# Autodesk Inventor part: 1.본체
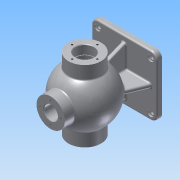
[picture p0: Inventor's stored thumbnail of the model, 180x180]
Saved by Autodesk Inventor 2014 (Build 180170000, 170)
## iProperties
Created: 2017-01
Part Number: 1.본체
Material: Aluminum 6061
Document SubType Name: Modeling
Designer: ksu
Density: 2.71 g/cm^3
Appearance: Aluminum - Flat
Mass: 1509 g
Surface Area: 1155.11 cm^2
Volume: 556.828 cm^3
Author: ksu
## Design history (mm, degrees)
sketch "Sketch1"
  geometry: L1 (-62.5, 57.5)-(62.5, 57.5); L2 (62.5, 57.5)-(62.5, -57.5); L3 (62.5, -57.5)-(-62.5, -57.5); L4 (-62.5, -57.5)-(-62.5, 57.5); L5 (-62.5, 57.5)-(62.5, -57.5); L6 (62.5, 57.5)-(-62.5, -57.5); 1 further point
  constraints: 12 end point, 2 midpoint, 2 parallel, 1 horizontal, 1 perpendicular
  dimensions: "d0" = 125 distance of L2.end L3.end; "d1" = 115 distance of L1.end L2.end
extrude "Extrusion1" new body sketch "Sketch1" distance "d2" = 10; taper "d3" = 0 deg
fillet "Fillet1" dims "d4" = 12
fillet "Fillet2" dims "d5" = 3
sketch "Sketch2"
  geometry: A1 r 9 centre (-50.5, 45.5) between (-50.5, 54.5) and (-59.5, 45.5) reference; A2 r 9 centre (-50.5, -45.5) between (-59.5, -45.5) and (-50.5, -54.5) reference; A3 r 9 centre (50.5, -45.5) between (50.5, -54.5) and (59.5, -45.5) reference; A4 r 9 centre (50.5, 45.5) between (59.5, 45.5) and (50.5, 54.5) reference; 5 further points
  constraints: 4 coincident
hole "Hole1" sketch "Sketch2" at (-50.5, 45.5), (-50.5, -45.5), (50.5, -45.5), (50.5, 45.5) diameter "d6" = 8; stored, may be unused: countersink angle "d10" = 90 deg, drill point angle "d12" = 118 deg; dims "d7" = 6, "d8" = 12, "d9" = 3, "d11" = 8
sketch "Sketch3"
  geometry: L1 (-50.5, 0)-(50.5, 0) reference; L2 (0, 150.015)-(0, -20.474); L3 (0, 138)-(0, 32); A1 r 53 centre (0, 85) between (0, 138) and (0, 32); 1 further point
  constraints: 4 end point, 2 point on circle, 2 point on line, 1 centre point, 1 collinear, 1 perpendicular
  dimensions: "d13" = 106 diameter of A1; "d14" = 85 distance from line of L1 A1.centre
revolve "Revolution1" sketch "Sketch3" stored, may be unused: angle "d15" = 90 deg
sketch "Sketch4"
  geometry: L1 (-62.5, 7)-(-62.5, 0) reference; L2 (62.5, 0)-(62.5, 7) reference; L3 (-50.5, 0)-(50.5, 0) reference; C1 r 31 at (0, 85); 1 further point
  constraints: 1 centre point
  dimensions: "d16" = 125 distance between parallel lines of L1 L2 (derived); "d17" = 62 diameter of C1; "d18" = 85 distance from line of L3 C1.centre
extrude "Extrusion2" join sketch "Sketch4" stored distance "d19" = 136; taper "d20" = 0 deg
workplane "Work Plane1"
sketch "Sketch5"
  geometry: C1 r 27 at (0, 0); 1 further point
  constraints: 1 centre point, 1 coincident
  dimensions: "d22" = 54 diameter of C1
extrude "Extrusion3" join sketch "Sketch5" distance "d23" = 65; taper "d24" = 0 deg
sketch "Sketch6"
  geometry: L1 (-59.5, 10)-(-50.5, 10) reference; L2 (50.5, 10)-(-50.5, 10) reference; L3 (50.5, 10)-(59.5, 10) reference; L4 (-50.5, 10)-(50.5, 10) reference; L5 (-52.5, 10)-(-35.28, 52.62); L6 (-62.5, 0)-(-62.5, 7) reference; L7 (52.5, 10)-(35.28, 52.62); L8 (62.5, 7)-(62.5, 0) reference; L9 (-35.28, 52.62)-(35.28, 52.62); L10 (-52.5, 10)-(52.5, 10); 1 further point
  constraints: 8 end point, 2 point on line, 1 collinear, 1 perpendicular
  dimensions: "d25" = 10 distance from line of L6 L5.start; "d26" = 22 deg angle of L6 L5; "d27" = 10 distance from line of L7.start L8; "d28" = 22 deg angle of L7 L8
extrude "Extrusion4" join sketch "Sketch6" stored distance "d29" = 8; taper "d30" = 0 deg
sketch "Sketch7"
  geometry: L1 (-45.5, 10)-(45.5, 10) reference; L2 (-51.5, 10)-(-39.5, 10) reference; L3 (-54.5, 10)-(-45.5, 10) reference; L4 (45.5, 10)-(54.5, 10) reference; L5 (-47.5, 10)-(-31.246, 50.23); L6 (-57.5, 0)-(-57.5, 7) reference; L7 (47.5, 10)-(31.246, 50.23); L8 (57.5, 7)-(57.5, 0) reference; L9 (-31.246, 50.23)-(31.246, 50.23); L10 (-47.5, 10)-(47.5, 10); A1 r 3 centre (-54.5, 7) between (-54.5, 10) and (-57.5, 7) reference; A2 r 3 centre (54.5, 7) between (57.5, 7) and (54.5, 10) reference; 1 further point
  constraints: 8 end point, 2 point on line, 1 collinear, 1 perpendicular
  dimensions: "d31" = 10 distance from line of L6 L5.start; "d32" = 22 deg angle of L6 L5; "d33" = 22 deg angle of L7 L8; "d34" = 10 distance from line of L8 L7.start
extrude "Extrusion5" join sketch "Sketch7" stored distance "d35" = 8; taper "d36" = 0 deg
fillet "Fillet3" dims "d37" = 3
fillet "Fillet4" dims "d38" = 3
fillet "Fillet5" dims "d39" = 3
sketch "Sketch8"
  geometry: L1 (-103.502, 85)-(116.5, 85); L2 (-43, 85)-(43, 85); A1 r 43 centre (0, 85) between (43, 85) and (-43, 85); 1 further point
  constraints: 4 end point, 3 point on line, 2 point on circle, 1 centre point, 1 collinear, 1 horizontal
  dimensions: "d40" = 85 distance from line of point (0, 0) L1; "d41" = 86 diameter of A1
revolve "Revolution2" sketch "Sketch8" stored, may be unused: angle "d42" = 90 deg
sketch "Sketch9"
  geometry: C1 r 31 at (0, 0) reference; C2 r 17.5 at (0, 0); 1 further point
  constraints: 1 centre point, 1 coincident
  dimensions: "d43" = 35 diameter of C2
extrude "Extrusion6" cut sketch "Sketch9" stored distance "d44" = 8; taper "d45" = 0 deg
sketch "Sketch10"
  geometry: L1 (68, 102.5)-(68, 67.5) reference; L2 (-76.217, 85)-(110.893, 85); L3 (52, 85)-(50.25, 85); L4 (50.25, 85)-(50.25, 66.5); L5 (50.25, 66.5)-(52, 66.5); L6 (52, 66.5)-(52, 85); 1 further point
  constraints: 10 end point, 2 parallel, 2 perpendicular, 1 horizontal, 1 point on line
  dimensions: "d46" = 85 distance from line of point (0, 0) L2; "d47" = 16 distance between parallel lines of L1 L6; "d48" = 37 diameter of L5 L2; "d49" = 1.75 distance between parallel lines of L4 L6
revolve "Revolution3" sketch "Sketch10" stored, may be unused: angle "d50" = 90 deg
chamfer "Chamfer1" distance "d51" = 1; stored, may be unused: second distance "d52" = 2, angle "d53" = 45 deg
sketch "Sketch11"
  geometry: C1 r 27 at (0, 0) reference; C2 r 13 at (0, 0)
  constraints: 1 centre point, 1 coincident
  dimensions: "d54" = 26 diameter of C2
extrude "Extrusion7" cut sketch "Sketch11" distance "d55" = 25; taper "d56" = 0 deg
fillet "Fillet6" dims "d57" = 3
chamfer "Chamfer2" distance "d58" = 1; stored, may be unused: second distance "d59" = 2, angle "d60" = 45 deg
sketch "Sketch12"
  geometry: C1 r 31 at (0, 0) reference; 2 further points
  dimensions: "d61" = 22.5 distance of point (0, 22.5) C1.centre
hole "Hole2" sketch "Sketch12" at (0, 22.5) diameter "d62" = 3.459; stored, may be unused: countersink angle "d66" = 90 deg, drill point angle "d68" = 118 deg; dims "d63" = 12, "d64" = 12, "d65" = 3, "d67" = 15
pattern_circular "Circular Pattern1" dims angle "d70" = 360 deg
sketch "Sketch13"
  geometry: C1 r 31 at (0, 0) reference; 2 further points
  dimensions: "d72" = 24 distance of point (0, -24) C1.centre
hole "Hole3" sketch "Sketch13" at (0, -24) diameter "d73" = 3.459; stored, may be unused: countersink angle "d77" = 90 deg, drill point angle "d79" = 118 deg; dims "d74" = 16, "d75" = 12, "d76" = 3, "d78" = 19
pattern_circular "Circular Pattern2" dims angle "d81" = 360 deg
sketch "Sketch14"
  geometry: L1 (143.002, 66.239)-(143.002, 24.761); L2 (143.002, 24.761)-(136.998, 24.761); L3 (136.998, 24.761)-(136.998, 66.239); L4 (136.998, 66.239)-(143.002, 66.239); L5 (143.002, 66.239)-(136.998, 24.761); L6 (143.002, 24.761)-(136.998, 66.239); L7 (150, 18.5)-(150, 72.5) reference; L8 (132.286, 72.5)-(132.286, 18.5) reference; L9 (132.286, 72.5)-(150, 72.5) reference; L10 (132.286, 18.5)-(150, 18.5) reference; 2 further points
  constraints: 4 end point, 1 midpoint, 2 other
  dimensions: "d83" = 27 distance from line of L9 point (140, 45.5); "d84" = 10 distance from line of L7 point (140, 45.5)
emboss "Emboss1" sketch "Sketch14" dims "d0" = 125, "d1" = 115, "d85" = 0.5, "d86" = 0
sketch "Sketch15"
  geometry: C1 r 27 at (0, 0) reference; 1 further point
  dimensions: "d87" = 20 distance of point (0, 20) C1.centre
hole "Hole4" sketch "Sketch15" at (0, 20) diameter "d88" = 3.459; stored, may be unused: countersink angle "d92" = 90 deg, drill point angle "d94" = 118 deg; dims "d89" = 9, "d90" = 12, "d91" = 3, "d93" = 11
pattern_circular "Circular Pattern3" dims angle "d96" = 360 deg
body "Solid1"
node "Projected Loop1"
other parameters: "d21" = -85
